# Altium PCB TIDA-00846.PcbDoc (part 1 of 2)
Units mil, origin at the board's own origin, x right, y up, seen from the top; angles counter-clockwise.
Board outline 4950 x 3450 mil, 2 copper layers (Top Layer, Bottom Layer), stack 62 mil thick; 90 components, 50 nets, 307 pads, 480 vias.
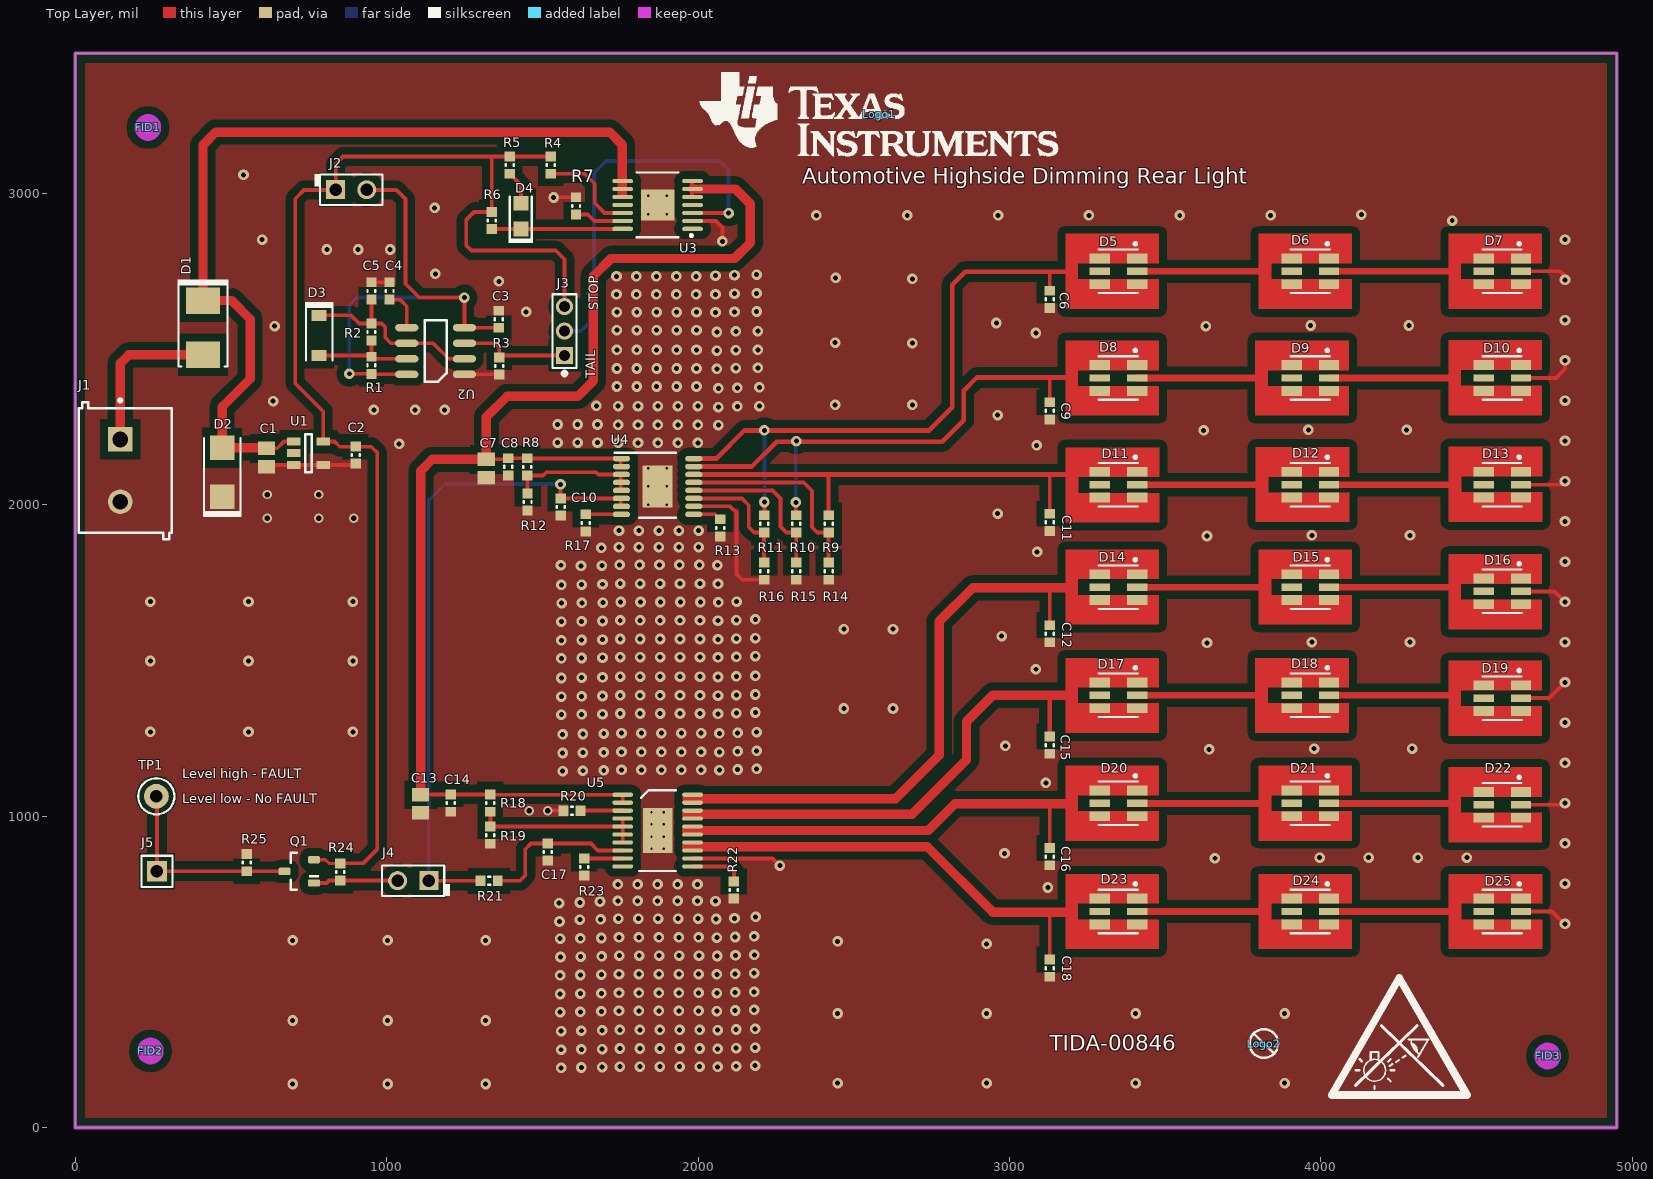
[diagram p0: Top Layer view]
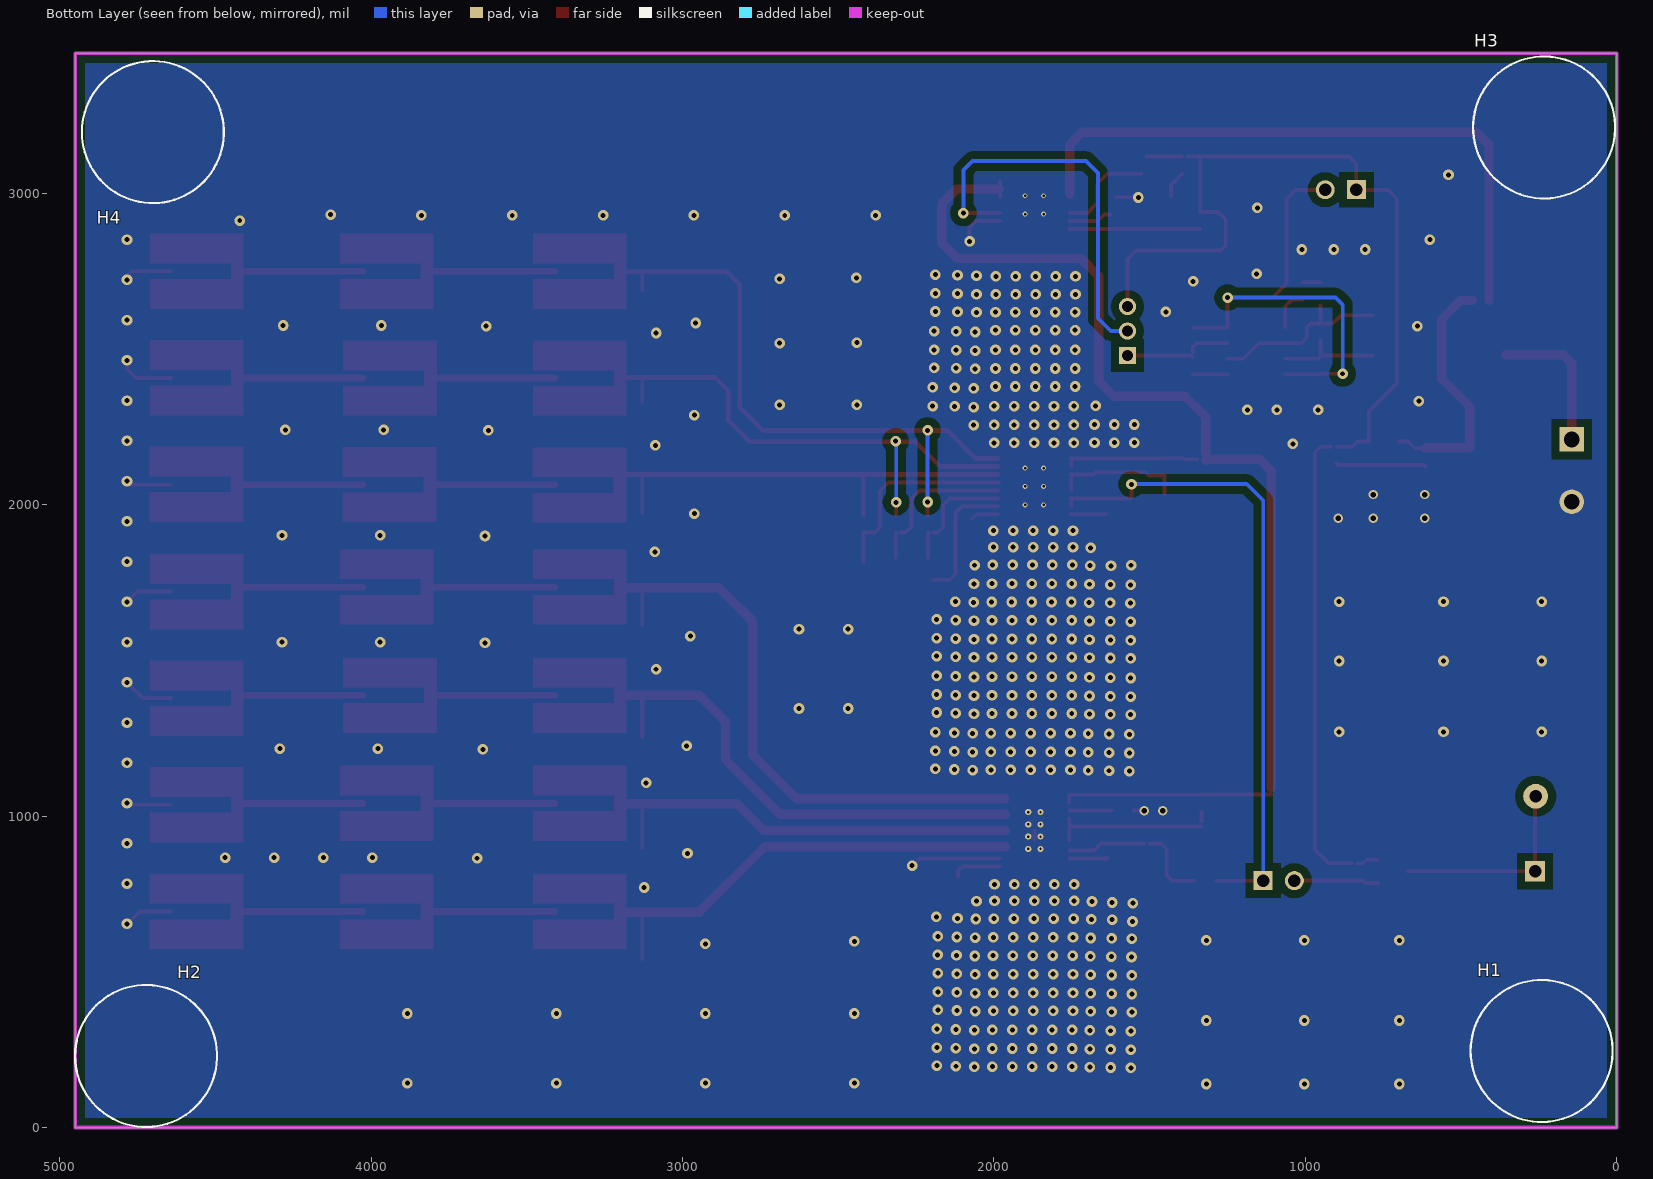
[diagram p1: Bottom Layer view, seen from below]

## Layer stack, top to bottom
Top Solder: solder mask 0.4, Solder Resist, Dk 3.5
Top Layer: signal copper 1.4
Dielectric1: core 59.2, FR-4, Dk 4.8
Bottom Layer: signal copper 1.4
Bottom Solder: solder mask 0.4, Solder Resist, Dk 3.5

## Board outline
0,0 4950,0 4950,3450 0,3450

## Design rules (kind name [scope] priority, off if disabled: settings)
AcuteAngle [All] p1: minimum=4.50000000000000E+0001 checktracksonly=FALSE
AssemblyTestPointUsage [All] p1: valid=2
Clearance Clearance_BoardEdge_MountingHoles [OnCopper and InComponentClass('Mounting Holes') vs IsKeepOut] p1: gap=40
Clearance Clearance_BoardEdge_Poly [OnCopper and InPoly vs IsKeepOut] p2: gap=25
Clearance Clearance_BoardEdge [OnCopper and Not InComponentClass('Logo') and not InComponentClass('FiducialMark') and not InRegion(1000,500,4000,800) and Not IsKeepout vs IsKeepOut] p3: gap=75
Clearance Clearance_Poly [InPolygon] p4: gap=25
Clearance [All] p5: gap=7.87
ComponentClearance ComponentClearance_Shunt [InComponentClass('Header') vs InComponentClass('Shunt')] p1: gap=0 collisioncheckmode=3 verticalgap=0 showdistances=FALSE
ComponentClearance ComponentClearance_MountingHoles_FiducialMarks [InComponentClass('Mounting Holes') vs InComponentClass('FiducialMark')] p2: gap=50 collisioncheckmode=3 verticalgap=10 showdistances=FALSE
ComponentClearance ComponentClearance_Logo [InComponentClass('Logo')] p3: gap=50 collisioncheckmode=3 verticalgap=10 showdistances=FALSE
ComponentClearance ComponentClearance_ScrewToNut [(HasFootprint('NY PMS 440 0025 PH')) vs (HasFootprint('Keystone_1902C'))] p4: gap=5 collisioncheckmode=3 verticalgap=10 showdistances=FALSE
ComponentClearance ComponentClearance_MountingHoles [InComponentClass('Mounting Holes')] p5: gap=250 collisioncheckmode=3 verticalgap=100000 showdistances=FALSE
ComponentClearance ComponentClearance_SmallPassives [HasFootprint('0201*') or HasFootprint('0402*') or HasFootprint('0508') or HasFootprint('0603*') or HasFootprint('0612') or HasFootprint('0805*') or HasFootprint('0815*') or HasFootprint('0830*') or HasFootprint('1206*') or HasFootprint('1210*') or HasFootprint('1808*') or HasFootprint('1812*') or HasFootprint('1825*') or HasFootprint('2010*') or HasFootprint('2220*') or HasFootprint('2225*') or HasFootprint('2512*') or HasFootprint('2728*') or HasFootprint('3518*') vs HasFootprint('0201*') or HasFootprint('0402*') or HasFootprint('0508') or HasFootprint('0603*') or HasFootprint('0612') or HasFootprint('0805*') or HasFootprint('0815*') or HasFootprint('0830*') or HasFootprint('1206*') or HasFootprint('1210*') or HasFootprint('1808*') or HasFootprint('1812*') or HasFootprint('1825*') or HasFootprint('2010*') or HasFootprint('2220*') or HasFootprint('2225*') or HasFootprint('2512*') or HasFootprint('2728*') or HasFootprint('3518*')] p6: gap=20 collisioncheckmode=3 verticalgap=10 showdistances=FALSE
ComponentClearance ComponentClearance_THtoSMT [IsThruComponent vs IsSMTComponent] p7: gap=100 collisioncheckmode=3 verticalgap=30 showdistances=FALSE
ComponentClearance ComponentClearance_THtoTH [IsThruComponent vs IsThruComponent] p8: gap=118.11 collisioncheckmode=3 verticalgap=30 showdistances=FALSE
ComponentClearance [All] p9: gap=40 collisioncheckmode=3 verticalgap=10 showdistances=FALSE
DiffPairsRouting [All] p1: maxlimit=100 minlimit=10 mostfreqgap=10 toplayer_minwidth=15 toplayer_maxwidth=15 toplayer_prefwidth=15 bottomlayer_minwidth=15 bottomlayer_maxwidth=15 bottomlayer_prefwidth=15 maxuncoupledlength=1000
FabricationTestPointUsage TestPointUsage [All] p1: valid=2 allowmultiple=FALSE
FabricationTestpoint Testpoint [All] p1: side=3 testpointundercomponent=TRUE minsize=40 maxsize=100 preferedsize=60 minholesize=0 maxholesize=40 preferedholesize=32 testpointgrid=1 allowsidetop=TRUE allowsidebottom=TRUE usegrid=TRUE gridtolerance=0.01
FanoutControl Fanout_LCC [IsLCC] p1: bgadir=Out bgaviamode=Centered fanoutstyle=Auto fanoutdirection=Alternating viagrid=1 // Fanout_LCC (Default Rule)
FanoutControl Fanout_BGA [IsBGA] p2: bgadir=Out bgaviamode=Centered fanoutstyle=Auto fanoutdirection=Alternating viagrid=1 // Fanout_BGA (Default Rule)
FanoutControl Fanout_Default [All] p4: bgadir=Out bgaviamode=Centered fanoutstyle=Auto fanoutdirection=Alternating viagrid=1 // Fanout_Default (Default Rule)
FanoutControl Fanout_Small [(CompPinCount < 5)] p5: bgadir=Out bgaviamode=Centered fanoutstyle=Auto fanoutdirection=OutThenIn viagrid=1 // Fanout_Small (Default Rule)
HoleSize [All] p1: absolutevalues=TRUE maxlimit=251 minlimit=6 maxpercent=80.000 minpercent=20.000
MinimumAnnularRing MinimumAnnularRing_ThermalPadVias [IsVia and InAnyComponent] p1: minimumring=2
MinimumAnnularRing [All] p2: minimumring=6
MinimumSolderMaskSliver MinimumSolderMaskSliver_Logo [InComponentClass('Logo') vs InComponentClass('Logo')] p1: minsoldermaskwidth=0.7
MinimumSolderMaskSliver [All] p2: minsoldermaskwidth=3.94
PlaneClearance [All] p1: clearance=8
PlaneConnect [All] p1: planeconnectstyle=Relief reliefexpansion=10 reliefentries=4 reliefconductorwidth=10 reliefairgap=10
PolygonConnect [All] p1: connectstyle=Direct reliefconductorwidth=10 reliefentries=4 polygonreliefangle="90 Angle" airgapwidth=10
RoutingVias ThermalPadVias [IsVia and InAnyComponent] p1: holewidth=7.87 width=19.68 viastyle="Through Hole" minholewidth=4 minwidth=12 maxholewidth=12.99 maxwidth=23.62
RoutingVias [All] p2: holewidth=16 width=34 viastyle="Through Hole" minholewidth=4 minwidth=26 maxholewidth=40 maxwidth=65
SMDToCorner [All] p1: distance=0
SilkToSilkClearance SilkToSilkClearance_Pb-FreeLogo [(HasFootprint('Pb-Free_Overlay_Medium') OR HasFootprint('Pb-Free_Overlay_Small')) vs (HasFootprint('Pb-Free_Overlay_Medium') OR HasFootprint('Pb-Free_Overlay_Small'))] p1: silktosilkclearance=0
SilkToSilkClearance [All] p2: silktosilkclearance=2
SilkToSolderMaskClearance SilkscreenOverComponentPads [IsPad] p1: minsilkscreentomaskgap=5 clearancetoexposedcopper=TRUE
SolderMaskExpansion [All] p1: expansion=1.97
UnpouredPolygon [All] p1: allowunpoured=FALSE
Width [All] p1: maxlimit=100 minlimit=6 preferedwidth=10 checkconnectedcopper=TRUE
14 further rules are at their usual default settings.

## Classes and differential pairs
component class Header: J2 J3 J4 J5
component class Logo: Logo1
component class Hardware_ANSI-B: FID1 FID2 FID3 H1 H2 H3 H4 Logo1 Logo2
component class FiducialMark: FID1 FID2 FID3
component class "High Dimming Project": C1 C2 C3 C4 C5 C6 C7 C8 C9 C10 C11 C12 C13 C14 C15 C16 C17 C18 D1 D2 D3 D4 D5 D6 D7 D8 D9 D10 D11 D12 D13 D14 D15 D16 D17 D18 D19 D20 D21 D22 D23 D24 D25 J1 J2 J3 J4 J5 Q1 R1 R2 R3 R4 R5 R6 R7 R8 R9 R10 R11 R12 R13 R14 R15 R16 R17 R18 R19 R20 R21 R22 R23 R24 R25 TP1 U1 U2 U3 U4 U5

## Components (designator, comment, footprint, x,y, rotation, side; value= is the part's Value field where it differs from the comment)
C1 "C2012X5R1H475K125AB" 0805L 613.84,2152.22 r270 top
C2 "CGB3B1X5R1A475K055AC" 0603L 900,2160 r270 top
C3 "C0603C225K8PACTU" 0603L 1360,2596 r90 top
C4 "0603ZC103KAT2A" 0603L 1009,2687 r90 top
C5 "06031C103JAT2A" 0603L 951,2687 r90 top
C6 "06031C103JAT2A" 0603L 3129,2660 r270 top
C7 "C2012X7R1H105K125AB" 0805L 1319.89,2117.09 r270 top
C8 "06031C103JAT2A" 0603L 1389.89,2122.09 r270 top
C9 "06031C103JAT2A" 0603L 3129,2302 r270 top
C10 "06031C103JAT2A" 0603L 1559,1993 r270 top
C11 "06031C103JAT2A" 0603L 3129,1944 r270 top
C12 "06031C103JAT2A" 0603L 3129,1586 r270 top
C13 "C2012X7R1H105K125AB" 0805L 1109,1040 r270 top
C14 "06031C103JAT2A" 0603L 1205.2,1042.12 r270 top
C15 "06031C103JAT2A" 0603L 3129,1228 r270 top
C16 "06031C103JAT2A" 0603L 3129,870 r270 top
C17 "06031C103JAT2A" 0603L 1517,885 r270 top
C18 "06031C103JAT2A" 0603L 3129,512 r270 top
D1 "10BQ040TRPBF" SMB 410,2569 r270 top
D2 "SMAJ30CA" SMA 471.84,2105 r90 top
D3 "1N4148W-7-F" SOD-123 783,2544 r270 top
D4 "LTST-C170KRKT" LED_LTST-C170 1431,2927 r270 top
D5 "LR G6SP-CBEA-1-1" LED_LR_G6SP 3350,2750 r270 top
D6 "LR G6SP-CBEA-1-1" LED_LR_G6SP 3966.5,2750 r270 top
D7 "LR G6SP-CBEA-1-1" LED_LR_G6SP 4583,2750 r270 top
D8 "LR G6SP-CBEA-1-1" LED_LR_G6SP 3350,2407.33 r270 top
D9 "LR G6SP-CBEA-1-1" LED_LR_G6SP 3966.5,2407.33 r270 top
D10 "LR G6SP-CBEA-1-1" LED_LR_G6SP 4583,2407.33 r270 top
D11 "LR G6SP-CBEA-1-1" LED_LR_G6SP 3350,2064.67 r270 top
D12 "LR G6SP-CBEA-1-1" LED_LR_G6SP 3966.5,2064.67 r270 top
D13 "LR G6SP-CBEA-1-1" LED_LR_G6SP 4583,2064.67 r270 top
D14 "LR G6SP-CBEA-1-1" LED_LR_G6SP 3350,1735.5 r270 top
D15 "LR G6SP-CBEA-1-1" LED_LR_G6SP 3966.5,1735.5 r270 top
D16 "LR G6SP-CBEA-1-1" LED_LR_G6SP 4583,1722 r270 top
D17 "LR G6SP-CBEA-1-1" LED_LR_G6SP 3350,1388.33 r270 top
D18 "LR G6SP-CBEA-1-1" LED_LR_G6SP 3966.5,1388.33 r270 top
D19 "LR G6SP-CBEA-1-1" LED_LR_G6SP 4583,1379.33 r270 top
D20 "LR G6SP-CBEA-1-1" LED_LR_G6SP 3350,1041.17 r270 top
D21 "LR G6SP-CBEA-1-1" LED_LR_G6SP 3966.5,1041.17 r270 top
D22 "LR G6SP-CBEA-1-1" LED_LR_G6SP 4583,1036.67 r270 top
D23 "LR G6SP-CBEA-1-1" LED_LR_G6SP 3350,694 r270 top
D24 "LR G6SP-CBEA-1-1" LED_LR_G6SP 3966.5,694 r270 top
D25 "LR G6SP-CBEA-1-1" LED_LR_G6SP 4583,694 r270 top
FID1 "Fiducial" Fiducial10-20 233,3212 r0 top
FID2 "Fiducial" Fiducial10-20 241,246 r0 top
FID3 "Fiducial" Fiducial10-20 4728,230 r0 top
H1 "SJ-5303 (CLEAR)" Bumpon_SJ5003Transparent 241,246 r90 bottom
H2 "SJ-5303 (CLEAR)" Bumpon_SJ5003Transparent 4723,230 r90 bottom
H3 "SJ-5303 (CLEAR)" Bumpon_SJ5003Transparent 233,3212 r90 bottom
H4 "SJ-5303 (CLEAR)" Bumpon_SJ5003Transparent 4701,3197 r90 bottom
J1 "OSTTC022162" On-Shore_OSTTC022162 160,2110 r270 top
J2 "HMTSW-102-07-G-S-240" SAMTEC_HMTSW-102-07-G-S-240 886,3012 r0 top
J3 "TMM-103-01-T-S" CONN_TMM-103-01-T-S 1571,2558 r90 top
J4 "HMTSW-102-07-G-S-240" SAMTEC_HMTSW-102-07-G-S-240 1085,793 r180 top
J5 "TSW-101-07-G-S" TSW-101-07-G-S 262,823 r90 top
Logo1 "Texas Instruments" TI_Stacked_Overlay_Medium 2581,3255 r0 top
Logo2 "Pb-Free Symbol" Pb-Free_Overlay_Small 3817,270 r0 top
Q1 "BC857C-7-F" SOT-23 718.94,822.92 r180 top
R1 "CRCW060334K8FKEA" 0603L 951,2448 r270 top
R2 "CRCW0603100KFKEA" 0603L 951,2555 r270 top
R3 "CRCW0603100KFKEA" 0603L 1361,2446 r90 top
R4 "CRCW060310K0JNEA" 0603L 1527,3091.05 r90 top
R5 "CRCW06031K00JNEA" 0603L 1395,3091.05 r90 top
R6 "CRCW06033K30JNEA" 0603L 1337,2913 r90 top
R7 "RC0603JR-070RL" 0603L 1608,2960 r90 top
R8 "CRCW060340K2FKEA" 0603L 1451,2122 r90 top
R9 "CRCW060335K7FKEA" 0603L 2419,1939 r90 top
R10 "CRCW060335K7FKEA" 0603L 2315.5,1939 r90 top
R11 "CRCW060335K7FKEA" 0603L 2212,1939 r90 top
R12 "CRCW060310K0JNEA" 0603L 1452.21,2009.09 r90 top
R13 "CRCW060312K1FKEA" 0603L 2071,1926 r90 top
R14 "CRCW060310K0FKEA" 0603L 2419,1787 r90 top
R15 "CRCW060310K0FKEA" 0603L 2315.5,1787 r90 top
R16 "CRCW060310K0FKEA" 0603L 2212,1787 r90 top
R17 "RC0603JR-070RL" 0603L 1639,1942 r90 top
R18 "CRCW060340K2FKEA" 0603L 1333,1042 r90 top
R19 "CRCW060310K0JNEA" 0603L 1333,939 r90 top
R20 "CRCW060310K0FKEA" 0603L 1595,1018 r0 top
R21 "RC0603JR-070RL" 0603L 1329,793 r180 top
R22 "CRCW06034K87FKEA" 0603L 2115,763 r90 top
R23 "RC0603JR-070RL" 0603L 1635,837 r90 top
R24 "CRCW06032K00FKEA" 0603L 851,821 r90 top
R25 "CRCW060310K0FKEA" 0603L 550,851 r270 top
TP1 "5002" Keystone5002 260,1064 r90 top
U1 "TPS7B6950QDBV" DBV0005A_N 748.84,2166 r0 top
U2 "TLC555-Q1" D0008A_L 1157,2494 r180 top
U3 "TPS1H100AQPWPRQ1" PWP0014C_N 1870,2963 r180 top
U4 "TPS92630QPWPRQ1" PWP0016F_N 1870,2059.09 r0 top
U5 "TPS92638QPWPRQ1" PWP0020B_N 1870,954 r0 top
? "Comment" LED_Warning 4252,287 r0 top

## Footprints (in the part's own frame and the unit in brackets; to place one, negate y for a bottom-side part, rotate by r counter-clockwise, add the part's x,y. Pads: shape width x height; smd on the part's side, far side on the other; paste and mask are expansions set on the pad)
0603L [mm] "0603 from SM-752 data"
  rect 0.8x0.85 smd: 1(-0.7,0) 2(0.7,0)
  silkscreen extent -0.07,-0.33 0.07,0.33, body extent -0.87,-0.47 0.87,0.47, height 0.85
0805L [mm] "0805 from SM-752 data"
  rect 1.1x1.4 smd: 1(-0.75,0) 2(0.75,0)
  body extent -1.1,-0.72 1.1,0.72, height 1.1
Bumpon_SJ5003Transparent [mil] "3M Hemispherical Bumpon transparent"
  round 1 on Mech4: 0(0,0)
  silkscreen extent -228,-228 228,228, body extent -217,-218 219,218, height 197
CONN_TMM-103-01-T-S [mil] "SAMTEC"
  rect 55x55 hole 35: 1(-78.74,0)
  round 55 hole 35: 2(0,0) 3(78.74,0)
  silkscreen extent -143,-39 118,39, body extent -118,-39 118,39, height 185
D0008A_L [mm] "SOIC, 8-Leads, Body 4.9x3.9mm, Pitch 1.27mm, IPC High Density"
  oval 1.9x0.6 smd: 1(-2.35,1.905) 2(-2.35,0.635) 3(-2.35,-0.635) 4(-2.35,-1.905) 5(2.35,-1.905) 6(2.35,-0.635) 7(2.35,0.635) 8(2.35,1.905)
  silkscreen extent -0.9,-2.5 0.9,2.5, body extent -3,-2.45 3,2.45, height 1.63
DBV0005A_N [mm] "SOT23, 5-Leads, Body 2.9x1.6mm, Pitch 0.95mm, Lead Span 2.8mm, IPC Medium Density"
  rect 1.1x0.65 smd: 1(-1.2,0.95) 2(-1.2,0) 3(-1.2,-0.95) 4(1.2,-0.95) 5(1.2,0.95)
  silkscreen extent -0.25,-1.55 0.25,1.55, body extent -1.42,-1.46 1.42,1.46, height 1.08
Fiducial10-20 [mm]
  round 1 smd mask+0.5: 1(0,0)
  Top Layer keep-out circle w1.178: c0,0 r0.5
Keystone5002 [mil] "For Keystone 500x miniature loop terminals"
  round 80 hole 40: 1(0,0)
  silkscreen extent -58,-58 58,58, body extent -49,-49 49,49, height 182
LED_LR_G6SP [mm] "OSRAM"
  rect 0.8x1.65 smd: 1(-1.05,1.525) 3(1.05,1.525) 4(1.05,-1.525) 6(-1.05,-1.525)
  rect 0.6x1.65 smd: 2(0,1.525) 5(0,-1.525)
  silkscreen extent -2.35,-1.63 1.78,1.6, body extent -1.75,-1.6 1.75,1.6, height 2.12
LED_LTST-C170 [mm] "LITE-ON"
  rect 1.2x1.2 smd: 1(-1.05,0) 2(1.05,0)
  silkscreen extent -1.6,-1 2.2,1, body extent -1.05,-0.67 1.05,0.67, height 1.1
LED_Warning [mil]
  silkscreen extent -217,-182 217,193
On-Shore_OSTTC022162 [mm] "THD, 2-Leads, Body 10.16x7.6mm, Pitch 5.08mm"
  rect 2x2 hole 1.3: 1(-2.54,-0.4)
  round 2 hole 1.3: 2(2.54,-0.4)
  silkscreen extent -5.85,-3.8 5.6,3.8, body extent -5.58,-3.8 5.6,3.8, height 10.31
Pb-Free_Overlay_Small [mil]
  silkscreen extent -46,-46 46,46
PWP0014C_N [mm] "TSOP, 14-Leads, Body 5x4.4mm, Pitch 0.65mm, Thermal Pad 3x3 mm, IPC Medium Density"
  oval 1.7x0.35 smd: 1(-2.85,1.95) 2(-2.85,1.3) 3(-2.85,0.65) 4(-2.85,0) 5(-2.85,-0.65) 6(-2.85,-1.3) 7(-2.85,-1.95) 8(2.85,-1.95) 9(2.85,-1.3) 10(2.85,-0.65) 11(2.85,0) 12(2.85,0.65) 13(2.85,1.3) 14(2.85,1.95)
  rect 2.72x2.5 smd: 15(0,0)
  silkscreen extent -2.85,-2.65 1.7,2.65, body extent -3.21,-2.5 3.21,2.5, height 0.99
PWP0016F_N [mm] "TSOP, 16-Leads, Body 5x4.4mm, Pitch 0.65mm, Thermal Pad 2.46x3.4 mm, IPC Medium Density"
  rrect100% 1.4x0.45 smd: 1(-2.95,2.275) 2(-2.95,1.625) 3(-2.95,0.975) 4(-2.95,0.325) 5(-2.95,-0.325) 6(-2.95,-0.975) 7(-2.95,-1.625) 8(-2.95,-2.275) 9(2.95,-2.275) 10(2.95,-1.625) 11(2.95,-0.975) 12(2.95,-0.325) 13(2.95,0.325) 14(2.95,0.975) 15(2.95,1.625) 16(2.95,2.275)
  rrect4% 2.46x3.4 smd: 17(0,0)
  silkscreen extent -3.5,-2.55 1.5,2.75, body extent -3.21,-2.5 3.21,2.5, height 1
PWP0020B_N [mm] "TSOP, 20-Leads, Body 6.5x4.4mm, Pitch 0.65mm, Thermal Pad 3.7x2.4 mm, IPC Medium Density"
  oval 1.7x0.35 smd: 1(-2.85,2.925) 2(-2.85,2.275) 3(-2.85,1.625) 4(-2.85,0.975) 5(-2.85,0.325) 6(-2.85,-0.325) 7(-2.85,-0.975) 8(-2.85,-1.625) 9(-2.85,-2.275) 10(-2.85,-2.925) 11(2.85,-2.925) 12(2.85,-2.275) 13(2.85,-1.625) 14(2.85,-0.975) 15(2.85,-0.325) 16(2.85,0.325) 17(2.85,0.975) 18(2.85,1.625) 19(2.85,2.275) 20(2.85,2.925)
  rect 2.4x3.7 smd: 21(0,0)
  silkscreen extent -1.5,-3.3 1.5,3.3, body extent -3.21,-3.25 3.21,3.25, height 0.98
SAMTEC_HMTSW-102-07-G-S-240 [mm] "Header, 2.54mm, 2x1, TH"
  rect 1.55x1.55 hole 1.02: 1(-1.27,0)
  round 1.55 hole 1.02: 2(1.27,0)
  silkscreen extent -3.01,-1.24 2.54,1.27, body extent -2.54,-1.27 2.54,1.27, height 8.64
SMA [mm] "Molded Diode, 2-Leads, Body 4.3x2.6mm, IPC Medium Density, based on OnSemi component dimensions and land pattern"
  rect 2x2 smd: 1(-2,0) 2(2,0)
  silkscreen extent -3.66,-1.57 2.79,1.57, body extent -2.6,-1.3 2.6,1.3, height 2.42
SMB [mil] "Molded Diode, 2-Leads, Body 5.4x3.6mm, IPC Medium Density, based on OnSemi component dimensions"
  rect 85x107.99 smd: 1(-87.01,0) 2(87.01,0)
  silkscreen extent -155,-82 125,82, body extent -106,-71 106,71, height 91
SOD-123 [mm] "On Semi recommended land pattern"
  rect 0.915x1.22 smd: 1(-1.637,0) 2(1.637,0)
  silkscreen extent -2.74,-1.17 2.03,1.17, body extent -1.93,-0.9 1.93,0.9, height 1.35
SOT-23 [mm] "SOT23, 3-Leads, Body 2.9x1.3mm, Pitch 0.95mm, Lead Span 2.5mm, IPC Medium Density"
  rrect50% 1x0.6 smd: 1(-1.2,0.95) 2(-1.2,-0.95) 3(1.2,0)
  silkscreen extent -1.62,-1.5 0.7,1.5, body extent -1.16,-1.45 1.21,1.45, height 1
TI_Stacked_Overlay_Medium [mil]
  silkscreen extent -576,-136 576,134
TSW-101-07-G-S [mm] "Samtec 100mil, 1pos, 230 mil above insulator"
  rect 1.65x1.65 hole 1.016 mask+0: 1(0,0)
  silkscreen extent -1.27,-1.27 1.27,1.27, body extent -1.27,-1.27 1.27,1.27, height 8.38

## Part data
C1: "CAP, CERM, 4.7 µF, 50 V, +/- 10%, X5R, 0805"
C2: "CAP, CERM, 4.7 µF, 10 V, +/- 10%, X5R, 0603"
C3: "CAP, CERM, 2.2 µF, 10 V, +/- 10%, X5R, 0603"
C4: "CAP, CERM, 0.01 µF, 10 V, +/- 10%, X7R, 0603"
C5 C6 C8 C9 C10 C11 C12 C14 C15 C16 C17 C18: "CAP, CERM, 0.01uF, 100V, +/-5%, X7R, 0603"
C7 C13: "CAP, CERM, 1 µF, 50 V, +/- 10%, X7R, 0805"
D1: "Diode, Schottky, 40V, 1A, SMB"
D2: "Diode, TVS, Bi, 30 V, 400 W, SMA"
D3: "Diode, Ultrafast, 100 V, 0.15 A, SOD-123"
D4 D5 D6 D7 D8 D9 D10 D11 D12 D13 D14 D15 D16 D17 D18 D19 D20 D21 D22 D23 D24 D25: "LED, Red, SMD"
FID1 FID2 FID3: "Fiducial mark.  There is nothing to buy or mount."
H1 H2 H3 H4: "Bumpon, Hemisphere, 0.44 X 0.20, Clear"
J1: "Terminal Block, 2-pole, 200mil, TH"
J2 J4: "Header, 100mil, 2x1, Gold, TH"
J3: "Header, 2mm, 3x1, Tin, TH"
J5: "Header, 100mil, 1pos, Gold, TH"
Logo1: library part TI_Logo, "Texas Instrument Corporate Signature"
Logo2: library part Pb-Free
Q1: library part "BC857C-7-F, Diodes Inc.", "Transistor, PNP, 45 V, 0.1 A, SOT-23"
R1: "RES, 34.8 k, 1%, 0.1 W, 0603"
R2 R3: "RES, 100 k, 1%, 0.1 W, 0603"
R4 R12 R19: "RES, 10 k, 5%, 0.1 W, 0603"
R5: "RES, 1.0 k, 5%, 0.1 W, 0603"
R6: "RES, 3.3 k, 5%, 0.1 W, 0603"
R7 R17 R21 R23: "RES, 0, 5%, 0.1 W, 0603"
R8 R18: "RES, 40.2 k, 1%, 0.1 W, 0603"
R9 R10 R11: "RES, 35.7 k, 1%, 0.1 W, 0603"
R13: "RES, 12.1 k, 1%, 0.1 W, 0603"
R14 R15 R16 R20 R25: "RES, 10.0 k, 1%, 0.1 W, 0603"
R22: "RES, 4.87 k, 1%, 0.1 W, 0603"
R24: "RES, 2.00 k, 1%, 0.1 W, 0603"
TP1: "Test Point, Miniature, White, TH"
U1: "High Voltage Ultra Low Iq - Low Drop Out Regulator, DBV0005A"
U2: library part TLC555CD, "LinCMOS Timer, D0008A"
U3: "40V/100mO Single Channel Smart High Side Switch, Automotive Qualified, PWP0014C"
U4: "Three-Channel Linear LED Driver with Analog and PWM Dimming, PWP0016F"
U5: "Eight-Channel Linear LED Driver with PWM Dimming, PWP0020B"

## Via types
v1: diameter 34, hole 16, Top Layer to Bottom Layer, 455 vias
v2: diameter 15.75, hole 7.87, Top Layer to Bottom Layer, 10 vias
v3: diameter 19.68, hole 7.87, Top Layer to Bottom Layer, 8 vias
v4: diameter 30, hole 18, Top Layer to Bottom Layer, 7 vias

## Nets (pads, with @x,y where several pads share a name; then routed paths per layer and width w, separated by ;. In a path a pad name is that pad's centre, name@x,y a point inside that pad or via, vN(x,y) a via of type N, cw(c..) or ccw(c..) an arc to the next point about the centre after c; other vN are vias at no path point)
+5V: C2.1 J2.1 J3.3 Q1.2 R4.2 R5.2 R6.2 R24.2 U1.5 | length 4198.9
  Top Layer w10: Q1.2@766.19,860.32 802.68,860.32 814.44,848.56 R24.2@834.27,848.56
  Top Layer w12: U1.5@816.44,2203.4 U1.5@796.09,2203.4 796.09,2299.91 706,2390 706,2983 734,3011 J2.1@836,3011 ; U1.5@817.74,2203.4 832.6,2203.4 849.44,2186.56 C2.1@898,2186.56 ; J2.1@836,3012 836,3095 859.61,3118.61 R5.2@1378.27,3118.61 ; R24.2@851,848.56 923.56,848.56 970,895 970,2167 950.44,2186.56 916.73,2186.56 ; 1337,3118 R6.2@1337,2940.56 1280.56,2940.56 1255,2915 1255,2834 1272,2817 1543,2817 1571,2789 J3.3@1571,2636.74 ; R5.2@1395,3118.61 R4.2@1510.27,3118.61
GND: C1.2 C2.2 C3.2 C4.2 C5.2 C6.2 C7.2 C8.2 C9.2 C10.2 C11.2 C12.2 C13.2 C14.2 C15.2 C16.2 C17.2 C18.2 D2.1 D7.2 D10.2 D13.2 D16.2 D19.2 D22.2 D25.2 J1.2 R3.1 R7.2 R12.1 R13.1 R14.1 R15.1 R16.1 R17.1 R19.1 R20.1 R22.1 R23.1 R25.1 U1.3 U1.4 U2.1 U3.2 U3.15 U4.10 U4.17 U5.12 U5.21 | length 2638.4
  Top Layer w12: C1.2@613.84,2122.69 C1.2@619.15,2128 ; U1.3@701.6,2128.6 619.75,2128.6 C1.2@619.15,2128 ; C2.2@900,2132.44 895.56,2128 C1.2@619.15,2128 ; C5.2@951,2714.56 C4.2@1009,2714.56 ; U2.1@1249.52,2419 1360.44,2419 R3.1@1361,2418.44 ; v4(1517,1018) R20.1@1551.69,1018 ; v1@1536.56,2987.56 R7.2@1608,2987.56 ; U5.21@1870,924 U5.21@1870,954 ; U5.12@1982.2,864.43 2239.37,864.43 v1(2262.8,841) ; U3.2@1982.2,2911.82 2057.18,2911.82 2078,2891 v1(2078,2846) ; U4.10@1986.14,1995.11 2102.89,1995.11 2123,1975 2123,1778 2141.56,1759.44 R16.1@2195.27,1759.44 ; D25.2@4643.04,694 4742,694 v1@4788,648 ; D22.2@4643.04,1036.67 4778.78,1036.67 v1(4784,1041.88) ; D19.2@4643.04,1379.33 4733.57,1379.33 v1(4784,1429.76) ; D16.2@4643.04,1722 4750.35,1722 v1(4784,1688.35) ; D13.2@4643.04,2064.67 4772.43,2064.67 v1(4784,2076.24) ; D10.2@4643.04,2407.33 4755.33,2407.33 4784,2436 v1(4784,2464.12) ; D7.2@4643.04,2750 4769,2750 v1@4784,2735
  other v1: 698,140 1002.8,140 1318,140 2448.2,143 2926.8,143 3405.4,143 3884,143 1560,192 1625,193 1692,194 2063,195 1749,196 1813,196 1877,196 1941,196 2005,196 2122,197 2183,199 1560,250 1625,251 1692,252 2063,253 1749,254 1813,254 1877,254 1941,254 2005,254 2122,255 2183,257 1560,310 1625,311 1692,312 2063,313 1749,314 1813,314 1877,314 1941,314 2005,314 2122,315 2183,317 698,344 1002.8,344 1318,344 2448.2,366.5 2926.8,366.5 3405.4,366.5 3884,366.5 1557,371 1622,372 1689,373 2060,374 1746,375 1810,375 1874,375 1938,375 2002,375 2119,376 2180,378 1557,429 1622,430 1689,431 2060,432 1746,433 1810,433 1874,433 1938,433 2002,433 2119,434 2180,436 1557,489 1622,490 1689,491 2060,492 1746,493 1810,493 1874,493 1938,493 2002,493 2119,494 2180,496 1558,548 1623,549 1690,550 2061,551 1747,552 1811,552 1875,552 1939,552 2003,552 2120,553 2181,555 2926.8,590 2448.2,598 698,601 1002.8,601 1318,601 1557,607 1622,608 1689,609 2060,610 1746,611 1810,611 1874,611 1938,611 2002,611 2119,612 2180,614 4784,654 1555,662 1620,668 1687,669 2058,670 1744,671 1808,671 1872,671 1936,671 2000,671 2117,672 2185,677 1554,721 1620,723 1685,726 2056,727 1742,728 1806,728 1870,728 1934,728 1998,728 3123,771 1742,781 1806,781 1870,781 1934,781 1998,781 4784,783.29 3659.4,865 3996.2,867 4153.8,867 4311.4,867 4469,867 2984,881 4784,912.59 3117,1107 1565,1145 1630,1146 1697,1147 2068,1148 1754,1149 1818,1149 1882,1149 1946,1149 2010,1149 2127,1150 2188,1152 4784,1171.18 1565,1203 1630,1204 1697,1205 2068,1206 1754,1207 1818,1207 1882,1207 1946,1207 2010,1207 2127,1208 2188,1210 3641.4,1215 3978.2,1217 4293.4,1217 2987,1226 1565,1263 1630,1264 1697,1265 2068,1266 1754,1267 1818,1267 1882,1267 1946,1267 2010,1267 2127,1268 2188,1270 241,1271 556.2,1271 891.4,1271 4784,1300.47 1561,1326 1626,1327 1693,1328 2064,1329 1750,1330 1814,1330 1878,1330 1942,1330 2006,1330 2123,1331 2184,1333 2468.4,1346 2626,1346 1561,1384 1626,1385 1693,1386 2064,1387 1750,1388 1814,1388 1878,1388 1942,1388 2006,1388 2123,1389 2184,1391 1561,1444 1626,1445 1693,1446 2064,1447 1750,1448 1814,1448 1878,1448 1942,1448 2006,1448 2123,1449 2184,1451 3085,1472 241,1498.5 556.2,1498.5 891.4,1498.5 1561,1507 1626,1508 1693,1509 2064,1510 1750,1511 1814,1511 1878,1511 1942,1511 2006,1511 2123,1512 2184,1514 3634.4,1557 3971.2,1559 4286.4,1559 4784,1559.06 1561,1565 1626,1566 1693,1567 2064,1568 1750,1569 1814,1569 1878,1569 1942,1569 2006,1569 2123,1570 2184,1572 2975,1578 2468.4,1601 2626,1601 1561,1625 1626,1626 1693,1627 2064,1628 1750,1629 1814,1629 1878,1629 1942,1629 2006,1629 2123,1630 2184,1632 1562,1684 1627,1685 1694,1686 2065,1687 1751,1688 1815,1688 1879,1688 1943,1688 2007,1688 241,1689 556.2,1689 891.4,1689 2124,1689 1561,1743 1626,1744 1693,1745 2064,1746 1750,1747 1814,1747 1878,1747 1942,1747 2006,1747 1624,1804 1691,1805 1559,1806 2062,1806 1748,1807 1812,1807 1876,1807 1940,1807 2004,1807 4784,1817.65 3089,1849 1689,1862 1746,1864 1810,1864 1874,1864 1938,1864 2002,1864 3634.4,1900 3971.2,1902 4286.4,1902 1746,1917 1810,1917 1874,1917 1938,1917 2002,1917 4784,1946.94 2962,1972 3087,2191 1040,2196 1743,2199 1807,2199 1871,2199 1935,2199 1999,2199 1549,2200 1613,2200 1677,2200 4784,2205.53 3623.4,2239 3960.2,2241 4275.4,2241 2065,2256 1743,2257 1807,2257 1871,2257 1935,2257 1999,2257 1549,2258 1613,2258 1677,2258 2962,2288 959,2305 1091,2305 1186,2305 2065,2314 2126,2316 1743,2317 1807,2317 1871,2317 1935,2317 1999,2317 2197,2317 1673,2318 2440,2321 2688,2321 635,2333 4784,2334.82 2065,2374 2126,2376 2197,2377 1739,2380 1803,2380 1867,2380 1931,2380 1995,2380 2060,2437 1739,2438 1803,2438 1867,2438 1931,2438 1995,2438 2121,2439 2192,2440 2060,2495 2121,2497 1739,2498 1803,2498 1867,2498 1931,2498 1995,2498 2192,2498 2688,2519 2440,2521 3085,2552 2060,2555 2121,2557 2192,2558 1739,2561 1803,2561 1867,2561 1931,2561 1995,2561 640,2574 3630.4,2574 3967.2,2576 4282.4,2576 2958,2584 4784,2593.41 2056,2618 1739,2619 1803,2619 1867,2619 1931,2619 1995,2619 1448,2620 2117,2620 2188,2621 1738,2676 1802,2676 1866,2676 1930,2676 1994,2676 2056,2676 2117,2678 2188,2679 1360,2718 4784,2722.71 2688,2726 2442,2729 1738,2734 1802,2734 1866,2734 1930,2734 1994,2734 2056,2736 2117,2738 2188,2739 1156,2742 808,2820 908,2820 1011,2820 600,2852 4784,2852 4422,2913 2380,2930 2671.71,2930 2963.43,2930 3255.14,2930 3546.86,2930 3838.57,2930 4130.29,2932 1154,2954 1536,2987 540,3060
  other v2: 1840.47,2000.03 1899.53,2000.03 1840.47,2059.09 1899.53,2059.09 1840.47,2118.14 1899.53,2118.14 1840.47,2933.47 1899.53,2933.47 1840.47,2992.53 1899.53,2992.53
  other v3: 1850.32,894.94 1889.68,894.94 1850.32,934.32 1889.68,934.32 1850.32,973.68 1889.68,973.68 1850.32,1013.06 1889.68,1013.06
  other v4: 1458,1018 615.84,1957 781.18,1957 893.84,1957 615.84,2033 781.84,2033
NetC1_1: C1.1 D1.1 D2.2 U1.1 U3.8 U3.9 U3.10 | length 2854.8
  Top Layer w12: C1.1@613.84,2181.75 648.59,2181.75 670.24,2203.4 U1.1@701.6,2203.4
  Top Layer w30: D1.1@410,2656.01 410,3156 451,3197 1716,3197 1756,3157 1756,2998 ; D1.1@464,2656.01 501.99,2656.01 562,2596 562,2405 471.84,2314.84 D2.2@471.84,2183.74 D2.2@475.84,2183.74 ; D2.2@472.85,2186.73 D2.2@475.84,2183.74 ; C1.1@613.84,2181.75 611.85,2183.74 D2.2@475.84,2183.74
NetC3_1: C3.1 J2.2 R1.2 U2.4 U2.8 | length 1612.3
  Top Layer w12: v1(880,2421) 950.44,2421 R1.2@951,2420.44 952.44,2419 U2.8@1064.48,2419 ; J2.2@933,3011 1031,3011 1060,2982 1060,2710 1104.48,2665.52 v1(1249.52,2665.52) U2.4@1249.52,2569 1359.44,2569 C3.1@1360,2568.44
  Bottom Layer w12: v1(880,2421) 880,2643 902.52,2665.52 v1(1249.52,2665.52)
NetC4_1: C4.1 U2.5 | length 133.1
  Top Layer w12: C4.1@1009,2659.44 1042.56,2659.44 1064.48,2637.52 U2.5@1064.48,2569
NetC5_1: C5.1 D3.1 R2.1 U2.2 U2.6 | length 602.3
  Top Layer w12: D3.1@783,2608.47 885.53,2608.47 911.44,2582.56 R2.1@951,2582.56 ; 951,2640.69 R2.1@951,2582.56 ; U2.2@1249.52,2469 1199,2469 1149,2519 U2.6@1064.48,2519 1013,2519 995,2537 995,2571 983.44,2582.56 R2.1@951,2582.56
